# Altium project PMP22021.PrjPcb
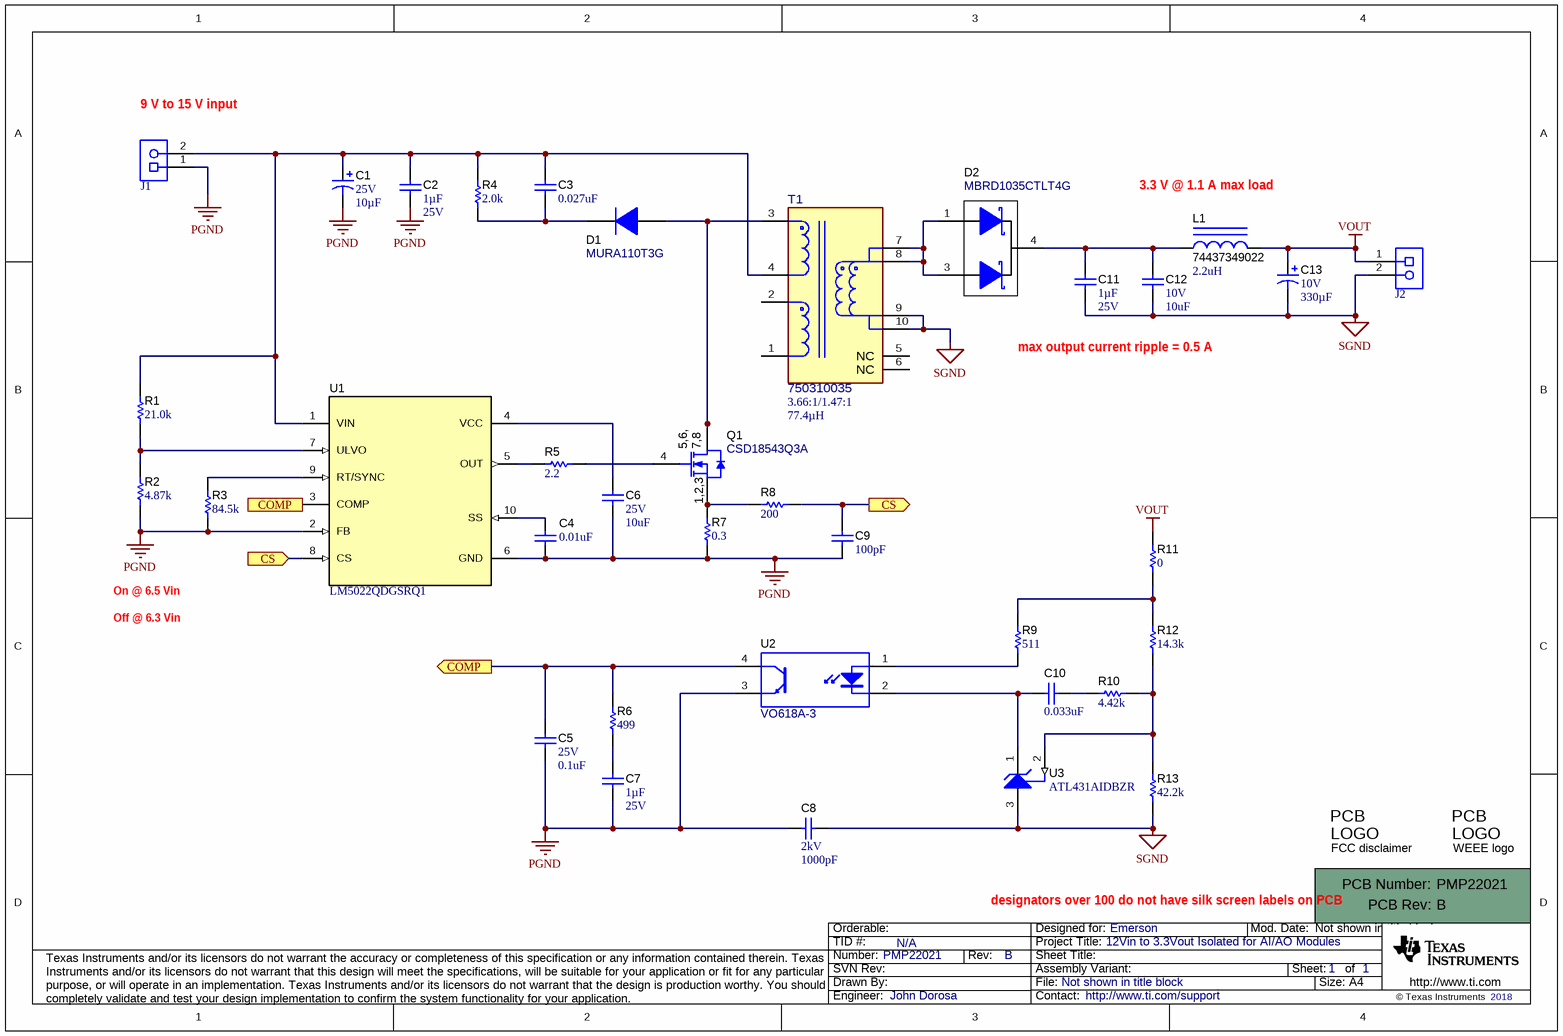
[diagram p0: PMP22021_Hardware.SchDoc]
TID: N/A; TechSupport: http://www.ti.com/support; SCH_Rev: B; PRJ_Title: 12Vin to 3.3Vout Isolated for AI/AO Modules; PRJ_Number: PMP22021; PRJ_Engineer: John Dorosa; PRJ_Customer: Emerson; PCB_Rev: B; PCB_Layout: John Dorosa; CopyrightYear: 2018
1 sheet, 39 parts. Net scope: flat (ports and power ports of the same name join across sheets).
Board file: PMP22021_PCB.PcbDoc

## Sheet PMP22021_Hardware.SchDoc
size A4; Date: Not shown in title block; ApprovedBy: Not shown in title block; CheckedBy: Not shown in title block; Author: Not shown in title block; CompanyName: Not shown in title block; Engineer: Not shown in title block; Organization: Not shown in title block; Address1: Not shown in title block; Address2: Not shown in title block; Address3: Not shown in title block; Address4: Not shown in title block; DocumentNumber: 1; Revision: Use project parameter SCH_Rev; SheetNumber: 1; SheetTotal: 1; PageSetup: Record=PageOptions¦CenterHorizontal=True¦CenterVertical=True¦PrintScale=1.00¦XCorrection=1.00¦YCorrection=1.00¦PrintKind=0¦BorderSize=5000000¦LeftOffset=0¦BottomOffset=0¦Orientation=2¦PaperLength=1000¦PaperWidth=1000¦Scale=100¦PaperSource=15¦PrintQuality=600¦MediaType=1¦DitherType=10¦PaperKind=Letter¦PrintScaleMode=1

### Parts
!PCB1  Printed Circuit Board  (value not drawn)  (mechanical)
C1  VDC_V: 25V  ValueDisplayed: 10µF  [WCAP-ATG5_500x1100]  (hidden comment: 860020472003)
C2  Cap_F: 1µF  VDC_V: 25V  [0805_HV]  (hidden comment: GRM219R71E105KA88D)
C3  value 0.027uF  [0603]  (hidden comment: GRM188R71H273KA61D)
C4  ValueDisplayed: 0.01uF  [0603]  (hidden comment: GCM188R71H103KA37D)
C5  VDC_V: 25V  ValueDisplayed: 0.1uF  [0603]  (hidden comment: GRM188R71E104KA01D)
C6  VDC_V: 25V  ValueDisplayed: 10uF  [1206_180]  (hidden comment: GRM31CR71E106KA12L)
C7  Cap_F: 1µF  VDC_V: 25V  [0603]  (hidden comment: GRM188R71E105KA12D)
C8  VDC_V: 2kV  ValueDisplayed: 1000pF  [1808]  (hidden comment: GR442QR73D102KW01L)
C9  Cap_F: 100pF  [0603]  (hidden comment: 06033C101KAT2A)
C10  ValueDisplayed: 0.033uF  [0603]  (hidden comment: GRM188R71C333KA01D)
C11  Cap_F: 1µF  VDC_V: 25V  [0603]  (hidden comment: GRM188R71E105KA12D)
C12  VDC_V: 10V  ValueDisplayed: 10uF  [1206]  (hidden comment: C3216X7R1A106K085AC)
C13  VDC_V: 10V  ValueDisplayed: 330µF  [WCAP-ATG8_630x1100]  (hidden comment: 860010273010)
D1  MURA110T3G  [SMA]
D2  MBRD1035CTLT4G  [DPAK]
J1  691214310002  [Wurth_691214310002]  (value not drawn)
J2  691214310002  [Wurth_691214310002]  (value not drawn)
L1  74437349022  ValueDisplayed: 2.2uH  [WE-LHMI_7050]
Logo1  FCC disclaimer  [FCC_disclaimer]  (no BOM)
Logo2  WEEE logo  [WEEE_Minimum]  (no BOM)
Q1  CSD18543Q3A  [DNH0008A]
R1  ValueDisplayed: 21.0k  [0603]  (hidden comment: CRCW060321K0FKEA)
R2  ValueDisplayed: 4.87k  [0603]  (hidden comment: CRCW06034K87FKEA)
R3  ValueDisplayed: 84.5k  [0603]  (hidden comment: CRCW060384K5FKEA)
R4  ValueDisplayed: 2.0k  [1206]  (hidden comment: CRCW12062K00JNEA)
R5  ValueDisplayed: 2.2  [0603]  (hidden comment: CRCW06032R20JNEA)
R6  ValueDisplayed: 499  [0603]  (hidden comment: CRCW0603499RFKEA)
R7  ValueDisplayed: 0.3  [1206]  (hidden comment: CSR1206FKR300)
R8  ValueDisplayed: 200  [0603]  (hidden comment: CRCW0603200RJNEA)
R9  ValueDisplayed: 511  [0603]  (hidden comment: CRCW0603511RFKEA)
R10  ValueDisplayed: 4.42k  [0603]  (hidden comment: CRCW06034K42FKEA)
R11  ValueDisplayed: 0  [0603]  (hidden comment: CRCW06030000Z0EA)
R12  ValueDisplayed: 14.3k  [0603]  (hidden comment: CRCW060314K3FKEA)
R13  ValueDisplayed: 42.2k  [0603]  (hidden comment: CRCW060342K2FKEA)
T1  750310035  Ns1toNp: 3.66:1/1.47:1  Ind_H: 77.4µH  [FP-750310035_SMT_17MM75_13MM46-MFG]
U1  LM5022QDGSRQ1  [DGS0010A_L]
U2  VO618A-3  [DIP-4]
U3  ATL431AIDBZR  [DBZ0003A_N]

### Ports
COMP (in), COMP (out), CS (in), CS (out)

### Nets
PGND: C1.2(-) C2.2 C4.1 C5.1 C6.2 C7.2 C8.2 C9.1 J1.1 R2.1 R3.2 R7.1 U1.2(FB) U1.6(GND) U2.3(E)
SGND: C8.1 C11.2 C12.2 C13.2(-) J2.2 R13.1 T1.9 T1.10 U3.3(ANODE)
VOUT: C13.1(+) J2.1 L1.2 R11.2
COMP: C5.2 R6.2 U1.3(COMP) U2.4(C) ; port COMP
CS: C9.2 R8.2 U1.8(CS) ; port CS
NetC1_1: C1.1(+) C2.1 C3.1 J1.2 R1.2 R4.2 T1.4 U1.1(VIN)
NetC3_2: C3.2 D1.1(K) R4.1
NetC4_2: C4.2 U1.10(SS)
NetC6_1: C6.1 U1.4(VCC)
NetC7_1: C7.1 R6.1
NetC10_1: C10.1 U2.2(K) U3.1(CATHODE)
NetC10_2: C10.2 R10.1
NetC11_1: C11.1 C12.1 D2.4(K) L1.1
NetD1_2: D1.2(A) Q1.5(D) Q1.6(D) Q1.7(D) Q1.8(D) Q1.9(D) T1.3
NetD2_1: D2.1(A) D2.3(A) T1.7 T1.8
NetQ1_1: Q1.1(S) Q1.2(S) Q1.3(S) R7.2 R8.1
NetQ1_4: Q1.4(G) R5.2
NetR1_1: R1.1 R2.2 U1.7(ULVO)
NetR3_1: R3.1 U1.9(RT/SYNC)
NetR5_1: R5.1 U1.5(OUT)
NetR9_1: R9.1 U2.1(A)
NetR9_2: R9.2 R11.1 R12.2
NetR10_2: R10.2 R12.1 R13.2 U3.2(REF)

Not connected (* = marked no-connect by the designer): T1 1 2 5(NC) 6(NC)

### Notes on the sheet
- (near J1) 9 V to 15 V input
- 3.3 V @ 1.1 A max load
- max output current ripple = 0.5 A
- Off @ 6.3 Vin
- On @ 6.5 Vin
- (near !PCB1) designators over 100 do not have silk screen labels on PCB

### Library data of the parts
!PCB1 = CMP-0003618-2: Manufacturer: Any; PartNumber: PMP22021
C1 = CMP-0860288-1: CAP, AL, 10 µF, 25 V, +/- 20%, TH; Manufacturer: Wurth Elektronik; AEC Qualified: N; Polarized: Y; SizeX_mm: 5; Value: 10uF; SizeZ_mm: 12.5; AEC Category: Q200; SizeArea_mm2: 25; SizeAreaWB_mm2: 49; TaMax_C: 105°C; TaMin_C: -40°C; Cap_Case: 5x11mm; CompType: Capacitor; U/M: EA
C2 = CMP-0008217-2: CAP, CERM, 1 uF, 25 V, +/- 10%, X7R, 0805; Manufacturer: MuRata; TaMin_C: -55°C; Polarized: N; SizeAreaWB_mm2: 6.75; Value1: Unknown; U/M: EA; Value: 1uF; TaMax_C: 125°C; SizeZ_mm: 1.45; SizeX_mm: 2; SizeY_mm: 1.25; Cap_Case: 0805; SizeArea_mm2: 2.5; AEC Category: Q200
C3 = CMP-0007448-4: CAP, CERM, 0.027 uF, 50 V, +/- 10%, X7R, 0603; Manufacturer: MuRata; TaMin_C: -55°C; Polarized: N; SizeAreaWB_mm2: 4.68; Value1: Unknown; U/M: EA; TaMax_C: 125°C; SizeZ_mm: 1; SizeX_mm: 1.6; SizeY_mm: 0.8; Value2: 50V; SizeArea_mm2: 1.28; Cap_F: 27nF; AEC Category: Q200
C4 = CMP-0007143-4: CAP, CERM, 0.01 uF, 50 V, +/- 10%, X7R, AEC-Q200 Grade 1, 0603; Manufacturer: MuRata; TaMin_C: -55°C; Polarized: N; SizeAreaWB_mm2: 4.68; Value1: Unknown; U/M: EA; Value: 0.01uF; TaMax_C: 125°C; SizeZ_mm: 1; SizeX_mm: 1.6; SizeY_mm: 0.8; Value2: 50V; SizeArea_mm2: 1.28; AEC Qualified: Y; Cap_F: 10nF; AEC Category: Q200
C5 = CMP-0007404-4: CAP, CERM, 0.1 uF, 25 V, +/- 10%, X7R, 0603; Manufacturer: MuRata; TaMin_C: -55°C; Polarized: N; SizeAreaWB_mm2: 4.68; Value1: Unknown; U/M: EA; Value: 0.1uF; TaMax_C: 125°C; SizeZ_mm: 1; SizeX_mm: 1.6; SizeY_mm: 0.8; SizeArea_mm2: 1.28; Cap_F: 100nF; AEC Category: Q200
C6 = CMP-0008965-2: CAP, CERM, 10 uF, 25 V, +/- 10%, X7R, 1206; Manufacturer: MuRata; TaMin_C: -55°C; Polarized: N; SizeAreaWB_mm2: 10.92; Value1: Unknown; U/M: EA; Value: 10uF; TaMax_C: 125°C; SizeZ_mm: 1.8; SizeX_mm: 3.2; SizeY_mm: 1.6; Cap_Case: 2220; SizeArea_mm2: 5.12; Cap_F: 10µF; AEC Category: Q200
C7 C11 = CMP-0007405-4: CAP, CERM, 1 uF, 25 V, +/- 10%, X7R, 0603; Manufacturer: MuRata; TaMin_C: -55°C; Polarized: N; SizeAreaWB_mm2: 4.68; Value1: Unknown; U/M: EA; Value: 1uF; TaMax_C: 125°C; SizeZ_mm: 1; SizeX_mm: 1.6; SizeY_mm: 0.8; SizeArea_mm2: 1.28; AEC Category: Q200
C8 = CMP-0009436-2: CAP, CERM, 1000 pF, 2000 V, +/- 10%, X7R, 1808; Manufacturer: MuRata; TaMin_C: -55°C; Polarized: N; SizeAreaWB_mm2: 16.5; Value1: Unknown; U/M: EA; Value: 1000pF; TaMax_C: 125°C; SizeZ_mm: 2.03; SizeX_mm: 4.5; SizeY_mm: 2; Value2: 2000V; SizeArea_mm2: 9; Cap_F: 1nF; AEC Category: Q200
C9 = CMP-0006751-4: CAP, CERM, 100 pF, 25 V, +/- 10%, X7R, 0603; Manufacturer: AVX; TaMin_C: -55°C; Polarized: N; SizeAreaWB_mm2: 4.68; Value1: Unknown; U/M: EA; Value: 100pF; TaMax_C: 125°C; SizeZ_mm: 1; SizeX_mm: 1.6; SizeY_mm: 0.8; Value2: 25V; SizeArea_mm2: 1.28; AEC Category: Q200
C10 = CMP-0007392-5: CAP, CERM, 0.033 uF, 16 V, +/- 10%, X7R, 0603; Manufacturer: MuRata; TaMin_C: -55°C; Polarized: N; SizeAreaWB_mm2: 4.68; Value1: Unknown; U/M: EA; TaMax_C: 125°C; SizeZ_mm: 1; SizeX_mm: 1.6; SizeY_mm: 0.8; Value2: 16V; SizeArea_mm2: 1.28; Cap_F: 33nF; AEC Category: Q200
C12 = CMP-0008687-2: CAP, CERM, 10 uF, 10 V, +/- 10%, X7R, 1206; Manufacturer: TDK; TaMin_C: -55°C; ESR_ohm: 2.454m; Polarized: N; SizeAreaWB_mm2: 10.92; Value1: 0.002454 ohm; U/M: EA; Value: 10uF; TaMax_C: 125°C; SizeZ_mm: 1.35; SizeX_mm: 3.2; SizeY_mm: 1.6; SizeArea_mm2: 5.12; Cap_F: 10µF; IRMS_A: 4.63182A; AEC Category: Q200
C13 = CMP-0860287-1: CAP, AL, 330 µF, 10 V, +/- 20%, TH; Manufacturer: Wurth Elektronik; Polarized: Y; U/M: EA; SizeX_mm: 6.3; AEC Category: Q200; TaMin_C: -40°C; SizeAreaWB_mm2: 68.89; TaMax_C: 85°C; AEC Qualified: N; SizeZ_mm: 12.5; Value: 330uF; Cap_Case: 6.3x11mm; SizeArea_mm2: 39.69; CompType: Capacitor
D1 = CMP-0029196-2: Diode, Ultrafast, 100 V, 2 A, SMA; Manufacturer: ON Semiconductor; SizeX_mm: 5.59; TJmax_C: 175°C; SizeAreaWB_mm2: 37.3428; Io_A: 2A; Green_REACh: Passed; SizeY_mm: 2.92; Value: 100V; Green_Lifecycle: Active; AEC Qualified: N; SizeArea_mm2: 16.3228; AEC Category: Q101; SizeZ_mm: 2.87
D2 = CMP-0028474-1: Diode, Schottky, 35 V, 10 A, DPAK; Manufacturer: ON Semiconductor; Io_A: 10A; Green_Lifecycle: Not Set; SizeAreaWB_mm2: 101.7114; Vr_V: 35V; Green_REACh: Incomplete; TJmax_C: 150°C; U/M: EA; Value: 35V; SizeZ_mm: 2.29; SizeX_mm: 9.91; SizeY_mm: 6.54; Vf_V: 560mV; Value2: 0.56V; SizeArea_mm2: 64.8114; AEC Category: Q101; RJC_CperW: 3
J1 J2 = CMP-0054822-2: Terminal Block, 2x1, 3.81mm, 24-16 AWG, 10A, 300VAC, TH; Manufacturer: Wurth Elektronik; CT: TRUE; CNHeader: FALSE; Green_Lifecycle: Active; Green_REACh: Passed
L1 = CMP-0064106-1: Inductor, Shielded Drum Core, Powdered Iron, 2.2 uH, 7.5 A, 0.0112 ohm, SMD; Manufacturer: Wurth Elektronik; Isat: 14A @ 20% inductance drop; Irms: 7.5A @ 40C rise; Green_Lifecycle: Active; SizeAreaWB_mm2: 73.96; DCR_ohm: 0.0112; Green_REACh: Passed; Value: 2.2uH; Imax_A: 7.5A; SizeZ_mm: 5; SizeX_mm: 6.6; SizeArea_mm2: 43.56; Ind_H: 2.2µH; AEC Category: Q200
Logo1 = CMP-0074847-1: FCC_disclaimer; Library Reference: Logo
Logo2 = CMP-0074769-1
Q1 = CMP-0000826-1: MOSFET, N-CH, 60 V, 35 A, DNH0008A (VSONP-8); Alternate Manufacturer: None; Manufacturer: Texas Instruments; SizeZ_mm: 0.9; ChType: N; Value2: 11.1 nC; Value1: 0.01; VdsMax_V: 60V; SizeX_mm: 3.3; SizeAreaWB_mm2: 18.49; Vgs_V: 20V; QgTyp_nC: 11.1; Value: 60V; Rdson45_ohm: 0.012; SizeArea_mm2: 10.89; AEC Category: Q101; IdsMax_A: 35A; U/M: EA
R1 = CMP-0022212-4: RES, 21.0 k, 1%, 0.1 W, AEC-Q200 Grade 0, 0603; Manufacturer: Vishay-Dale; Power_W: 100mW; TempCo: 100 ppm/C; Value_Code: 21k0; Value: 21.0k; EIA_Code: E96; Res_ohm: 21k; SizeX_mm: 1.6; SizeY_mm: 0.8; SizeZ_mm: 1; Value2: 0.1W; SizeArea_mm2: 1.28; AEC Qualified: Y; VDC_V: 75V; AEC Category: Q200; AEC Grade: 0
R2 = CMP-0022457-4: RES, 4.87 k, 1%, 0.1 W, AEC-Q200 Grade 0, 0603; Manufacturer: Vishay-Dale; Power_W: 100mW; TempCo: 100 ppm/C; Value_Code: 4k87; Value: 4.87k; EIA_Code: E96; SizeX_mm: 1.6; SizeY_mm: 0.8; SizeZ_mm: 1; Value2: 0.1W; SizeArea_mm2: 1.28; AEC Qualified: Y; VDC_V: 75V; AEC Category: Q200; AEC Grade: 0
R3 = CMP-0022624-4: RES, 84.5 k, 1%, 0.1 W, AEC-Q200 Grade 0, 0603; Manufacturer: Vishay-Dale; Power_W: 100mW; TempCo: 100 ppm/C; Value: 84.5k; EIA_Code: E96; SizeX_mm: 1.6; SizeY_mm: 0.8; Value_Code: 84k5; SizeZ_mm: 1; Value2: 0.1W; SizeArea_mm2: 1.28; AEC Qualified: Y; VDC_V: 75V; AEC Category: Q200; AEC Grade: 0
R4 = CMP-0018640-3: RES, 2.0 k, 5%, 0.25 W, AEC-Q200 Grade 0, 1206; Manufacturer: Vishay-Dale; Power_W: 250mW; TempCo: 200 ppm/C; Value_Code: 2k00; Value: 2.0k; EIA_Code: E24; Res_ohm: 2k; SizeX_mm: 3.2; SizeY_mm: 1.6; SizeZ_mm: 1.35; Value2: 0.25W; SizeArea_mm2: 5.12; AEC Qualified: Y; VDC_V: 200V; AEC Category: Q200; AEC Grade: 0
R5 = CMP-0025777-4: RES, 2.2, 5%, 0.1 W, AEC-Q200 Grade 0, 0603; Manufacturer: Vishay-Dale; Power_W: 100mW; TempCo: 200 ppm/C; Value_Code: 2R20; Value: 2.2; EIA_Code: E24; SizeX_mm: 1.6; SizeY_mm: 0.8; SizeZ_mm: 1; Value2: 0.1W; SizeArea_mm2: 1.28; AEC Qualified: Y; VDC_V: 75V; AEC Category: Q200; AEC Grade: 0
R6 = CMP-0022446-5: RES, 499, 1%, 0.1 W, AEC-Q200 Grade 0, 0603; Manufacturer: Vishay-Dale; Power_W: 100mW; TempCo: 100 ppm/C; Value_Code: 499R; Value: 499; EIA_Code: E96; SizeX_mm: 1.6; SizeY_mm: 0.8; SizeZ_mm: 1; Value2: 0.1W; SizeArea_mm2: 1.28; AEC Qualified: Y; VDC_V: 75V; AEC Category: Q200; AEC Grade: 0
R7 = CMP-0017268-2: RES, 0.3, 1%, 0.5 W, 1206; Manufacturer: Stackpole Electronics Inc; Power_W: 500mW; TempCo: 100 ppm/C; Value_Code: R300; U/M: EA; Value: 0.3; EIA_Code: E96; SizeX_mm: 3.2; SizeY_mm: 1.6; SizeZ_mm: 1.35; Value2: 0.5W; SizeArea_mm2: 5.12; AEC Category: Q200
R8 = CMP-0025752-4: RES, 200, 5%, 0.1 W, AEC-Q200 Grade 0, 0603; Manufacturer: Vishay-Dale; Power_W: 100mW; TempCo: 200 ppm/C; Value_Code: 200R; Value: 200; EIA_Code: E24; SizeX_mm: 1.6; SizeY_mm: 0.8; SizeZ_mm: 1; Value2: 0.1W; SizeArea_mm2: 1.28; AEC Qualified: Y; VDC_V: 75V; AEC Category: Q200; AEC Grade: 0
R9 = CMP-0022481-5: RES, 511, 1%, 0.1 W, AEC-Q200 Grade 0, 0603; Manufacturer: Vishay-Dale; Power_W: 100mW; TempCo: 100 ppm/C; Value_Code: 511R; Value: 511; EIA_Code: E96; SizeX_mm: 1.6; SizeY_mm: 0.8; SizeZ_mm: 1; Value2: 0.1W; SizeArea_mm2: 1.28; AEC Qualified: Y; VDC_V: 75V; AEC Category: Q200; AEC Grade: 0
R10 = CMP-0022453-4: RES, 4.42 k, 1%, 0.1 W, AEC-Q200 Grade 0, 0603; Manufacturer: Vishay-Dale; Power_W: 100mW; TempCo: 100 ppm/C; Value_Code: 4k42; Value: 4.42k; EIA_Code: E96; SizeX_mm: 1.6; SizeY_mm: 0.8; SizeZ_mm: 1; Value2: 0.1W; SizeArea_mm2: 1.28; AEC Qualified: Y; VDC_V: 75V; AEC Category: Q200; AEC Grade: 0
R11 = CMP-0025697-4: RES, 0, 5%, 0.1 W, AEC-Q200 Grade 0, 0603; Manufacturer: Vishay-Dale; Power_W: 100mW; TempCo: 200 ppm/C; Value_Code: 0000; Value: 0; EIA_Code: E24; SizeX_mm: 1.6; SizeY_mm: 0.8; SizeZ_mm: 1; Value2: 0.1W; SizeArea_mm2: 1.28; AEC Qualified: Y; VDC_V: 75V; AEC Category: Q200
R12 = CMP-0022055-4: RES, 14.3 k, 1%, 0.1 W, AEC-Q200 Grade 0, 0603; Manufacturer: Vishay-Dale; Power_W: 100mW; TempCo: 100 ppm/C; Value_Code: 14k3; Value: 14.3k; EIA_Code: E96; SizeX_mm: 1.6; SizeY_mm: 0.8; SizeZ_mm: 1; Value2: 0.1W; SizeArea_mm2: 1.28; AEC Qualified: Y; VDC_V: 75V; AEC Category: Q200; AEC Grade: 0
R13 = CMP-0022418-4: RES, 42.2 k, 1%, 0.1 W, AEC-Q200 Grade 0, 0603; Manufacturer: Vishay-Dale; Power_W: 100mW; TempCo: 100 ppm/C; Value_Code: 42k2; Value: 42.2k; EIA_Code: E96; SizeX_mm: 1.6; SizeY_mm: 0.8; SizeZ_mm: 1; Value2: 0.1W; SizeArea_mm2: 1.28; AEC Qualified: Y; VDC_V: 75V; AEC Category: Q200; AEC Grade: 0
T1 = CMP-0087256-1: MID-POE Power Over Ethernet Transformer; Manufacturer: Wurth Electronik; DCR_ohm: 0.22; AEC Qualified: No; SizeZ_mm: 12.7mm
U1 = CMP-0076391-1: 2.2MHz 60-V Low Side Controller for Boost, SEPIC and Flyback, DGS0010A (VSSOP-10); Manufacturer: Texas Instruments; Alternate PartNumber: LM5022QDGSTQ1; SizeAreaWB_mm2: 23.6; SizeArea_mm2: 14.7; SizeZ_mm: 1.1; SizeY_mm: 3.0; U/M: EA; CompType: IC; SizeX_mm: 4.9
U2 = CMP-0083653-1: Optocoupler, 5.3 kV, 100-200% CTR, SMT; Manufacturer: Vishay-Semiconductor; CTR (Max): 200%; SizeAreaWB_mm2: 71.064; CTR (Min): 100%; SizeZ_mm: 5; SizeX_mm: 8.8; SizeY_mm: 4.58; SizeArea_mm2: 40.304; Voltage_Isolation_Vrms: 5.3kV
U3 = CMP-0066199-1: 2.5V Low Iq Adjustable Precision Shunt Regulator, DBZ0003A (SOT-23-3); Alternate Manufacturer: Texas Instruments; SizeAreaWB_mm2: 14.0; U/M: EA; SizeZ_mm: 1.12; SizeX_mm: 2.5; SizeY_mm: 3.0; SizeArea_mm2: 7.5; CompType: IC

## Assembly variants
001: not fitted D2 D3 R10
